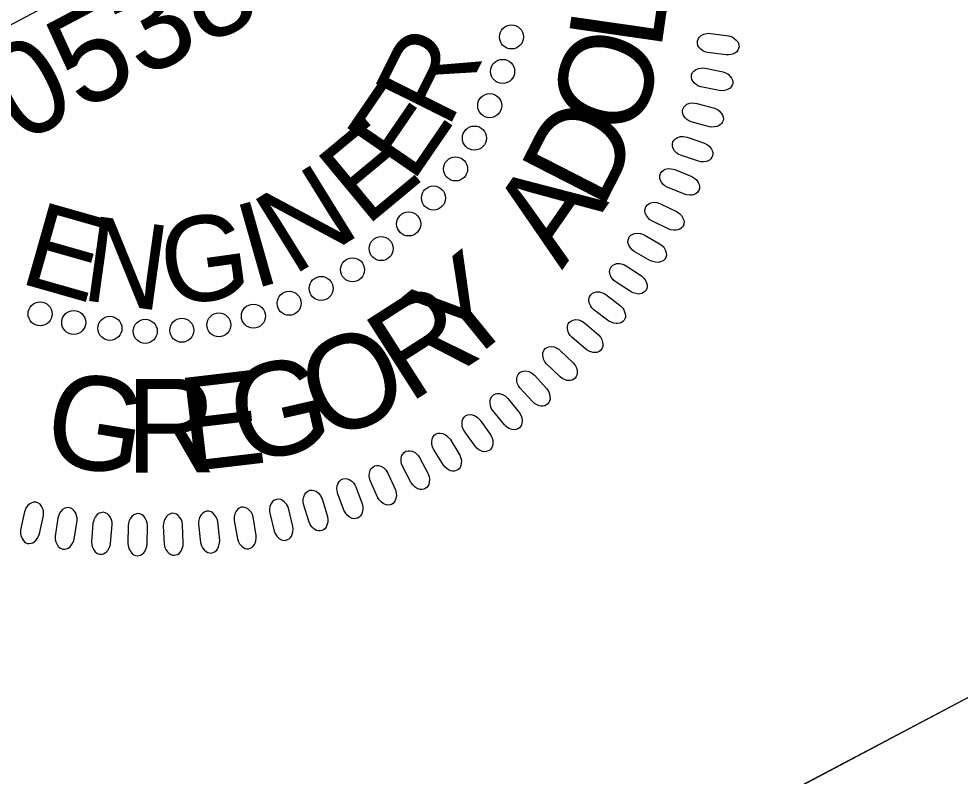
# Model space of a CAD drawing. Extents: x 1486990 to 1489232, y 497582 to 499336.
# Drawn here: x 1488528 to 1488578.8, y 499157.9 to 499198.8 of the extents above; entities that cross this region are included whole.
import ezdxf

# ---------------------------------------------------------------- set-up
doc = ezdxf.new("R2010")
doc.units = 0
for name, color, linetype in [('DTM Contours Minor', 7, 'Continuous'), ('PROF-MAJR', 7, 'Continuous'), ('Prop Drainage Structure Catch Basin Open Throat 1 CELL', 7, 'Continuous'), ('Prop Drainage Structure Drop Inlet Adjust CELL', 7, 'Continuous')]:
    doc.layers.add(name, color=color, linetype=linetype)

msp = doc.modelspace()

# ---------------------------------------------------------------- linework, layer by layer
at = {"layer": 'DTM Contours Minor'}
msp.add_line((1488428.293, 499082.427), (1488605.185, 499175.83), dxfattribs=at)
msp.add_line((1488428.293, 499082.427), (1488605.185, 499175.83), dxfattribs=at)
at = {"layer": 'PROF-MAJR'}
for points in [[(1488565.357, 499197.978), (1488566.34, 499197.837), (1488566.512, 499197.781), (1488566.618, 499197.724), (1488566.741, 499197.615), (1488566.818, 499197.524), (1488566.869, 499197.424), (1488566.889, 499197.337), (1488566.892, 499197.244), (1488566.863, 499197.157), (1488566.825, 499197.064), (1488566.766, 499196.987), (1488566.673, 499196.915), (1488566.602, 499196.876), (1488566.474, 499196.839), (1488566.323, 499196.812), (1488566.193, 499196.812), (1488565.185, 499196.95), (1488565.052, 499196.988), (1488564.945, 499197.04), (1488564.827, 499197.13), (1488564.728, 499197.236), (1488564.675, 499197.323), (1488564.645, 499197.456), (1488564.647, 499197.578), (1488564.696, 499197.693), (1488564.748, 499197.772), (1488564.842, 499197.863), (1488564.992, 499197.939), (1488565.144, 499197.972), (1488565.251, 499197.981)], [(1488565.062, 499196.1), (1488566.035, 499195.897), (1488566.203, 499195.831), (1488566.305, 499195.767), (1488566.421, 499195.65), (1488566.492, 499195.555), (1488566.537, 499195.452), (1488566.551, 499195.363), (1488566.548, 499195.27), (1488566.513, 499195.186), (1488566.47, 499195.095), (1488566.406, 499195.023), (1488566.309, 499194.956), (1488566.236, 499194.922), (1488566.106, 499194.893), (1488565.954, 499194.875), (1488565.824, 499194.884), (1488564.826, 499195.085), (1488564.695, 499195.131), (1488564.592, 499195.19), (1488564.481, 499195.287), (1488564.388, 499195.399), (1488564.341, 499195.49), (1488564.319, 499195.624), (1488564.329, 499195.746), (1488564.385, 499195.858), (1488564.442, 499195.932), (1488564.542, 499196.017), (1488564.695, 499196.083), (1488564.849, 499196.107), (1488564.957, 499196.109)], [(1488564.606, 499194.199), (1488565.564, 499193.936), (1488565.727, 499193.86), (1488565.825, 499193.789), (1488565.934, 499193.665), (1488565.998, 499193.566), (1488566.037, 499193.461), (1488566.045, 499193.371), (1488566.036, 499193.279), (1488565.997, 499193.195), (1488565.948, 499193.108), (1488565.88, 499193.04), (1488565.778, 499192.979), (1488565.704, 499192.95), (1488565.572, 499192.929), (1488565.419, 499192.921), (1488565.29, 499192.937), (1488564.307, 499193.202), (1488564.179, 499193.255), (1488564.079, 499193.321), (1488563.974, 499193.425), (1488563.889, 499193.542), (1488563.848, 499193.635), (1488563.834, 499193.771), (1488563.852, 499193.892), (1488563.915, 499194), (1488563.976, 499194.071), (1488564.081, 499194.149), (1488564.239, 499194.206), (1488564.394, 499194.22), (1488564.502, 499194.216)], [(1488564.092, 499192.376), (1488565.032, 499192.053), (1488565.19, 499191.967), (1488565.284, 499191.89), (1488565.384, 499191.76), (1488565.443, 499191.656), (1488565.474, 499191.549), (1488565.477, 499191.459), (1488565.463, 499191.367), (1488565.418, 499191.287), (1488565.364, 499191.203), (1488565.291, 499191.139), (1488565.186, 499191.085), (1488565.109, 499191.06), (1488564.977, 499191.048), (1488564.824, 499191.049), (1488564.696, 499191.074), (1488563.731, 499191.399), (1488563.607, 499191.461), (1488563.512, 499191.533), (1488563.413, 499191.643), (1488563.336, 499191.765), (1488563.301, 499191.861), (1488563.296, 499191.997), (1488563.32, 499192.117), (1488563.39, 499192.22), (1488563.456, 499192.287), (1488563.566, 499192.359), (1488563.726, 499192.406), (1488563.882, 499192.41), (1488563.989, 499192.399)], [(1488563.43, 499190.625), (1488564.348, 499190.244), (1488564.501, 499190.148), (1488564.589, 499190.065), (1488564.681, 499189.929), (1488564.733, 499189.822), (1488564.757, 499189.713), (1488564.755, 499189.623), (1488564.735, 499189.533), (1488564.685, 499189.456), (1488564.625, 499189.375), (1488564.548, 499189.315), (1488564.441, 499189.268), (1488564.363, 499189.248), (1488564.23, 499189.244), (1488564.077, 499189.255), (1488563.951, 499189.288), (1488563.009, 499189.673), (1488562.889, 499189.743), (1488562.799, 499189.82), (1488562.707, 499189.936), (1488562.637, 499190.063), (1488562.608, 499190.161), (1488562.612, 499190.297), (1488562.643, 499190.415), (1488562.72, 499190.514), (1488562.79, 499190.577), (1488562.904, 499190.641), (1488563.067, 499190.678), (1488563.223, 499190.673), (1488563.329, 499190.655)], [(1488562.658, 499188.782), (1488563.549, 499188.344), (1488563.695, 499188.239), (1488563.779, 499188.152), (1488563.862, 499188.009), (1488563.907, 499187.899), (1488563.925, 499187.789), (1488563.916, 499187.699), (1488563.89, 499187.61), (1488563.836, 499187.536), (1488563.772, 499187.46), (1488563.691, 499187.405), (1488563.581, 499187.365), (1488563.502, 499187.349), (1488563.369, 499187.354), (1488563.217, 499187.375), (1488563.093, 499187.415), (1488562.177, 499187.858), (1488562.062, 499187.936), (1488561.977, 499188.018), (1488561.892, 499188.14), (1488561.83, 499188.271), (1488561.807, 499188.371), (1488561.82, 499188.506), (1488561.859, 499188.622), (1488561.942, 499188.716), (1488562.015, 499188.775), (1488562.133, 499188.832), (1488562.298, 499188.858), (1488562.454, 499188.843), (1488562.558, 499188.818)], [(1488561.768, 499187.096), (1488562.631, 499186.602), (1488562.77, 499186.488), (1488562.847, 499186.395), (1488562.921, 499186.248), (1488562.96, 499186.135), (1488562.97, 499186.024), (1488562.957, 499185.935), (1488562.925, 499185.848), (1488562.866, 499185.777), (1488562.797, 499185.705), (1488562.713, 499185.655), (1488562.601, 499185.622), (1488562.521, 499185.612), (1488562.388, 499185.625), (1488562.238, 499185.655), (1488562.117, 499185.703), (1488561.231, 499186.203), (1488561.12, 499186.288), (1488561.04, 499186.375), (1488560.964, 499186.502), (1488560.911, 499186.637), (1488560.894, 499186.738), (1488560.915, 499186.872), (1488560.961, 499186.986), (1488561.049, 499187.075), (1488561.127, 499187.128), (1488561.247, 499187.178), (1488561.415, 499187.193), (1488561.568, 499187.168), (1488561.671, 499187.137)], [(1488560.798, 499185.432), (1488561.628, 499184.885), (1488561.759, 499184.763), (1488561.831, 499184.665), (1488561.896, 499184.514), (1488561.926, 499184.399), (1488561.93, 499184.288), (1488561.911, 499184.199), (1488561.874, 499184.114), (1488561.811, 499184.048), (1488561.737, 499183.98), (1488561.651, 499183.936), (1488561.536, 499183.91), (1488561.456, 499183.904), (1488561.324, 499183.926), (1488561.176, 499183.965), (1488561.058, 499184.021), (1488560.205, 499184.576), (1488560.1, 499184.666), (1488560.026, 499184.759), (1488559.958, 499184.891), (1488559.913, 499185.028), (1488559.902, 499185.13), (1488559.932, 499185.263), (1488559.985, 499185.373), (1488560.079, 499185.456), (1488560.159, 499185.505), (1488560.283, 499185.547), (1488560.451, 499185.552), (1488560.603, 499185.517), (1488560.703, 499185.48)], [(1488559.695, 499183.875), (1488560.489, 499183.277), (1488560.613, 499183.147), (1488560.678, 499183.045), (1488560.733, 499182.889), (1488560.757, 499182.773), (1488560.753, 499182.662), (1488560.729, 499182.575), (1488560.686, 499182.492), (1488560.619, 499182.43), (1488560.541, 499182.367), (1488560.452, 499182.328), (1488560.336, 499182.309), (1488560.256, 499182.309), (1488560.126, 499182.338), (1488559.981, 499182.387), (1488559.866, 499182.45), (1488559.05, 499183.058), (1488558.951, 499183.155), (1488558.882, 499183.252), (1488558.823, 499183.387), (1488558.787, 499183.528), (1488558.783, 499183.63), (1488558.82, 499183.761), (1488558.881, 499183.867), (1488558.979, 499183.944), (1488559.062, 499183.987), (1488559.188, 499184.022), (1488559.356, 499184.016), (1488559.506, 499183.972), (1488559.604, 499183.928)], [(1488558.552, 499182.349), (1488559.307, 499181.702), (1488559.422, 499181.563), (1488559.481, 499181.458), (1488559.526, 499181.3), (1488559.542, 499181.182), (1488559.532, 499181.071), (1488559.502, 499180.986), (1488559.455, 499180.906), (1488559.384, 499180.848), (1488559.302, 499180.79), (1488559.21, 499180.757), (1488559.094, 499180.745), (1488559.013, 499180.75), (1488558.886, 499180.788), (1488558.744, 499180.846), (1488558.634, 499180.916), (1488557.857, 499181.573), (1488557.764, 499181.676), (1488557.702, 499181.777), (1488557.651, 499181.917), (1488557.624, 499182.059), (1488557.626, 499182.161), (1488557.671, 499182.289), (1488557.739, 499182.392), (1488557.842, 499182.463), (1488557.928, 499182.501), (1488558.056, 499182.526), (1488558.223, 499182.51), (1488558.37, 499182.458), (1488558.464, 499182.408)], [(1488557.236, 499180.866), (1488557.948, 499180.174), (1488558.055, 499180.028), (1488558.107, 499179.919), (1488558.142, 499179.758), (1488558.151, 499179.64), (1488558.134, 499179.529), (1488558.098, 499179.446), (1488558.046, 499179.37), (1488557.971, 499179.316), (1488557.887, 499179.263), (1488557.793, 499179.236), (1488557.676, 499179.232), (1488557.595, 499179.242), (1488557.471, 499179.288), (1488557.332, 499179.354), (1488557.227, 499179.431), (1488556.493, 499180.136), (1488556.407, 499180.245), (1488556.351, 499180.349), (1488556.309, 499180.491), (1488556.291, 499180.635), (1488556.3, 499180.737), (1488556.354, 499180.862), (1488556.426, 499180.96), (1488556.534, 499181.024), (1488556.622, 499181.057), (1488556.752, 499181.075), (1488556.917, 499181.048), (1488557.06, 499180.986), (1488557.152, 499180.931)], [(1488555.848, 499179.518), (1488556.517, 499178.782), (1488556.613, 499178.63), (1488556.658, 499178.518), (1488556.683, 499178.355), (1488556.685, 499178.236), (1488556.661, 499178.127), (1488556.62, 499178.047), (1488556.563, 499177.974), (1488556.486, 499177.925), (1488556.397, 499177.877), (1488556.302, 499177.856), (1488556.185, 499177.859), (1488556.106, 499177.874), (1488555.984, 499177.928), (1488555.85, 499178.003), (1488555.75, 499178.086), (1488555.061, 499178.835), (1488554.982, 499178.95), (1488554.933, 499179.057), (1488554.9, 499179.202), (1488554.891, 499179.347), (1488554.906, 499179.448), (1488554.968, 499179.569), (1488555.047, 499179.663), (1488555.158, 499179.72), (1488555.248, 499179.747), (1488555.378, 499179.757), (1488555.542, 499179.72), (1488555.681, 499179.649), (1488555.769, 499179.587)], [(1488554.415, 499178.268), (1488555.035, 499177.491), (1488555.123, 499177.334), (1488555.161, 499177.219), (1488555.176, 499177.055), (1488555.169, 499176.936), (1488555.139, 499176.829), (1488555.093, 499176.751), (1488555.031, 499176.681), (1488554.95, 499176.638), (1488554.86, 499176.596), (1488554.763, 499176.581), (1488554.647, 499176.591), (1488554.569, 499176.611), (1488554.45, 499176.672), (1488554.322, 499176.755), (1488554.227, 499176.845), (1488553.586, 499177.636), (1488553.515, 499177.754), (1488553.473, 499177.866), (1488553.449, 499178.012), (1488553.449, 499178.157), (1488553.47, 499178.257), (1488553.539, 499178.374), (1488553.624, 499178.462), (1488553.739, 499178.512), (1488553.83, 499178.534), (1488553.961, 499178.535), (1488554.122, 499178.488), (1488554.256, 499178.408), (1488554.34, 499178.342)], [(1488552.913, 499177.097), (1488553.483, 499176.284), (1488553.56, 499176.121), (1488553.591, 499176.004), (1488553.595, 499175.839), (1488553.582, 499175.721), (1488553.544, 499175.616), (1488553.494, 499175.541), (1488553.428, 499175.476), (1488553.345, 499175.437), (1488553.251, 499175.401), (1488553.155, 499175.392), (1488553.038, 499175.41), (1488552.962, 499175.435), (1488552.847, 499175.503), (1488552.724, 499175.594), (1488552.635, 499175.689), (1488552.046, 499176.519), (1488551.982, 499176.642), (1488551.947, 499176.756), (1488551.932, 499176.903), (1488551.941, 499177.047), (1488551.969, 499177.146), (1488552.045, 499177.259), (1488552.136, 499177.342), (1488552.253, 499177.384), (1488552.346, 499177.4), (1488552.476, 499177.393), (1488552.634, 499177.336), (1488552.763, 499177.248), (1488552.842, 499177.176)], [(1488551.292, 499176.063), (1488551.81, 499175.215), (1488551.877, 499175.048), (1488551.9, 499174.93), (1488551.894, 499174.765), (1488551.873, 499174.648), (1488551.829, 499174.545), (1488551.774, 499174.474), (1488551.705, 499174.413), (1488551.619, 499174.38), (1488551.524, 499174.349), (1488551.426, 499174.346), (1488551.311, 499174.371), (1488551.236, 499174.401), (1488551.127, 499174.476), (1488551.01, 499174.575), (1488550.927, 499174.676), (1488550.39, 499175.541), (1488550.334, 499175.667), (1488550.307, 499175.783), (1488550.302, 499175.931), (1488550.32, 499176.075), (1488550.353, 499176.171), (1488550.436, 499176.279), (1488550.532, 499176.356), (1488550.651, 499176.391), (1488550.745, 499176.401), (1488550.875, 499176.386), (1488551.029, 499176.319), (1488551.152, 499176.223), (1488551.227, 499176.147)], [(1488549.643, 499175.08), (1488550.107, 499174.201), (1488550.163, 499174.03), (1488550.178, 499173.91), (1488550.162, 499173.746), (1488550.134, 499173.63), (1488550.084, 499173.531), (1488550.024, 499173.463), (1488549.951, 499173.407), (1488549.864, 499173.378), (1488549.766, 499173.354), (1488549.669, 499173.357), (1488549.556, 499173.39), (1488549.483, 499173.424), (1488549.378, 499173.506), (1488549.268, 499173.612), (1488549.191, 499173.718), (1488548.711, 499174.615), (1488548.663, 499174.744), (1488548.642, 499174.862), (1488548.646, 499175.01), (1488548.673, 499175.152), (1488548.713, 499175.247), (1488548.803, 499175.349), (1488548.903, 499175.419), (1488549.024, 499175.447), (1488549.118, 499175.451), (1488549.247, 499175.428), (1488549.396, 499175.352), (1488549.513, 499175.248), (1488549.583, 499175.167)], [(1488547.93, 499174.241), (1488548.338, 499173.334), (1488548.383, 499173.16), (1488548.392, 499173.039), (1488548.365, 499172.877), (1488548.33, 499172.763), (1488548.274, 499172.668), (1488548.21, 499172.603), (1488548.133, 499172.551), (1488548.044, 499172.529), (1488547.946, 499172.511), (1488547.849, 499172.52), (1488547.738, 499172.559), (1488547.667, 499172.598), (1488547.568, 499172.686), (1488547.464, 499172.799), (1488547.394, 499172.91), (1488546.971, 499173.835), (1488546.931, 499173.968), (1488546.918, 499174.086), (1488546.931, 499174.233), (1488546.967, 499174.374), (1488547.013, 499174.465), (1488547.109, 499174.561), (1488547.213, 499174.626), (1488547.337, 499174.646), (1488547.43, 499174.644), (1488547.557, 499174.613), (1488547.702, 499174.527), (1488547.812, 499174.417), (1488547.876, 499174.331)], [(1488546.196, 499173.505), (1488546.546, 499172.575), (1488546.58, 499172.398), (1488546.581, 499172.277), (1488546.544, 499172.117), (1488546.502, 499172.006), (1488546.44, 499171.913), (1488546.372, 499171.853), (1488546.292, 499171.806), (1488546.202, 499171.79), (1488546.102, 499171.778), (1488546.006, 499171.793), (1488545.899, 499171.84), (1488545.83, 499171.883), (1488545.736, 499171.977), (1488545.64, 499172.096), (1488545.577, 499172.21), (1488545.213, 499173.16), (1488545.182, 499173.295), (1488545.176, 499173.414), (1488545.198, 499173.561), (1488545.243, 499173.699), (1488545.294, 499173.787), (1488545.396, 499173.877), (1488545.504, 499173.935), (1488545.629, 499173.947), (1488545.722, 499173.939), (1488545.847, 499173.9), (1488545.985, 499173.805), (1488546.088, 499173.688), (1488546.148, 499173.599)], [(1488544.378, 499172.843), (1488544.669, 499171.893), (1488544.692, 499171.714), (1488544.685, 499171.594), (1488544.639, 499171.436), (1488544.589, 499171.328), (1488544.521, 499171.239), (1488544.45, 499171.184), (1488544.367, 499171.142), (1488544.276, 499171.131), (1488544.176, 499171.125), (1488544.081, 499171.147), (1488543.977, 499171.199), (1488543.911, 499171.247), (1488543.824, 499171.347), (1488543.735, 499171.472), (1488543.679, 499171.59), (1488543.376, 499172.561), (1488543.353, 499172.698), (1488543.355, 499172.817), (1488543.386, 499172.961), (1488543.44, 499173.096), (1488543.496, 499173.181), (1488543.603, 499173.264), (1488543.715, 499173.315), (1488543.84, 499173.32), (1488543.933, 499173.306), (1488544.055, 499173.26), (1488544.187, 499173.156), (1488544.282, 499173.033), (1488544.335, 499172.94)], [(1488528.303, 499172.142), (1488528.1, 499171.169), (1488528.094, 499170.989), (1488528.112, 499170.869), (1488528.173, 499170.716), (1488528.233, 499170.613), (1488528.308, 499170.531), (1488528.384, 499170.482), (1488528.47, 499170.448), (1488528.561, 499170.446), (1488528.662, 499170.45), (1488528.754, 499170.48), (1488528.854, 499170.542), (1488528.915, 499170.595), (1488528.993, 499170.702), (1488529.07, 499170.835), (1488529.114, 499170.958), (1488529.327, 499171.953), (1488529.338, 499172.091), (1488529.325, 499172.21), (1488529.28, 499172.35), (1488529.215, 499172.48), (1488529.151, 499172.56), (1488529.036, 499172.632), (1488528.921, 499172.673), (1488528.796, 499172.666), (1488528.704, 499172.643), (1488528.587, 499172.586), (1488528.465, 499172.471), (1488528.381, 499172.339), (1488528.336, 499172.242)], [(1488541.558, 499172.074), (1488541.789, 499171.108), (1488541.859, 499170.943), (1488541.927, 499170.842), (1488542.047, 499170.729), (1488542.144, 499170.661), (1488542.248, 499170.62), (1488542.338, 499170.608), (1488542.43, 499170.613), (1488542.514, 499170.65), (1488542.603, 499170.697), (1488542.674, 499170.763), (1488542.738, 499170.861), (1488542.77, 499170.935), (1488542.794, 499171.066), (1488542.808, 499171.219), (1488542.795, 499171.349), (1488542.565, 499172.34), (1488542.515, 499172.469), (1488542.453, 499172.571), (1488542.353, 499172.68), (1488542.239, 499172.769), (1488542.147, 499172.813), (1488542.012, 499172.831), (1488541.891, 499172.818), (1488541.78, 499172.758), (1488541.707, 499172.699), (1488541.625, 499172.597), (1488541.564, 499172.441), (1488541.544, 499172.287), (1488541.545, 499172.179)], [(1488530.108, 499171.813), (1488529.968, 499170.829), (1488529.972, 499170.649), (1488529.998, 499170.531), (1488530.068, 499170.382), (1488530.134, 499170.283), (1488530.215, 499170.206), (1488530.294, 499170.162), (1488530.382, 499170.133), (1488530.474, 499170.136), (1488530.573, 499170.147), (1488530.664, 499170.182), (1488530.759, 499170.25), (1488530.816, 499170.307), (1488530.887, 499170.42), (1488530.956, 499170.557), (1488530.993, 499170.682), (1488531.143, 499171.688), (1488531.145, 499171.827), (1488531.124, 499171.944), (1488531.071, 499172.082), (1488530.998, 499172.208), (1488530.929, 499172.282), (1488530.81, 499172.349), (1488530.692, 499172.382), (1488530.567, 499172.367), (1488530.478, 499172.339), (1488530.364, 499172.274), (1488530.249, 499172.151), (1488530.174, 499172.015), (1488530.136, 499171.914)], [(1488532.005, 499171.521), (1488531.927, 499170.53), (1488531.942, 499170.35), (1488531.975, 499170.234), (1488532.055, 499170.09), (1488532.126, 499169.995), (1488532.212, 499169.924), (1488532.294, 499169.884), (1488532.383, 499169.861), (1488532.475, 499169.87), (1488532.574, 499169.886), (1488532.662, 499169.928), (1488532.753, 499170.002), (1488532.806, 499170.063), (1488532.87, 499170.179), (1488532.93, 499170.32), (1488532.958, 499170.447), (1488533.045, 499171.461), (1488533.038, 499171.6), (1488533.011, 499171.715), (1488532.949, 499171.85), (1488532.867, 499171.97), (1488532.793, 499172.041), (1488532.671, 499172.1), (1488532.552, 499172.125), (1488532.428, 499172.102), (1488532.34, 499172.069), (1488532.231, 499171.997), (1488532.124, 499171.868), (1488532.058, 499171.726), (1488532.025, 499171.624)], [(1488533.91, 499171.413), (1488533.894, 499170.42), (1488533.921, 499170.242), (1488533.961, 499170.128), (1488534.05, 499169.989), (1488534.127, 499169.899), (1488534.217, 499169.833), (1488534.301, 499169.799), (1488534.392, 499169.781), (1488534.482, 499169.796), (1488534.58, 499169.819), (1488534.666, 499169.865), (1488534.752, 499169.945), (1488534.801, 499170.008), (1488534.858, 499170.129), (1488534.909, 499170.274), (1488534.929, 499170.403), (1488534.952, 499171.42), (1488534.936, 499171.557), (1488534.901, 499171.672), (1488534.831, 499171.802), (1488534.743, 499171.917), (1488534.665, 499171.983), (1488534.538, 499172.033), (1488534.418, 499172.051), (1488534.296, 499172.021), (1488534.211, 499171.982), (1488534.106, 499171.903), (1488534.008, 499171.767), (1488533.95, 499171.623), (1488533.924, 499171.519)], [(1488535.804, 499171.4), (1488535.85, 499170.408), (1488535.888, 499170.232), (1488535.936, 499170.121), (1488536.033, 499169.988), (1488536.116, 499169.902), (1488536.209, 499169.842), (1488536.295, 499169.814), (1488536.387, 499169.802), (1488536.477, 499169.823), (1488536.572, 499169.851), (1488536.655, 499169.903), (1488536.736, 499169.988), (1488536.782, 499170.055), (1488536.83, 499170.178), (1488536.872, 499170.326), (1488536.884, 499170.456), (1488536.844, 499171.473), (1488536.819, 499171.609), (1488536.777, 499171.72), (1488536.699, 499171.846), (1488536.603, 499171.955), (1488536.521, 499172.016), (1488536.392, 499172.058), (1488536.27, 499172.069), (1488536.151, 499172.031), (1488536.068, 499171.987), (1488535.969, 499171.902), (1488535.879, 499171.76), (1488535.831, 499171.612), (1488535.812, 499171.506)], [(1488537.709, 499171.484), (1488537.817, 499170.496), (1488537.867, 499170.322), (1488537.921, 499170.215), (1488538.026, 499170.088), (1488538.114, 499170.008), (1488538.212, 499169.954), (1488538.299, 499169.931), (1488538.392, 499169.925), (1488538.479, 499169.951), (1488538.573, 499169.985), (1488538.653, 499170.042), (1488538.728, 499170.132), (1488538.769, 499170.202), (1488538.81, 499170.328), (1488538.842, 499170.478), (1488538.847, 499170.608), (1488538.742, 499171.621), (1488538.709, 499171.755), (1488538.66, 499171.863), (1488538.574, 499171.984), (1488538.472, 499172.087), (1488538.386, 499172.143), (1488538.255, 499172.177), (1488538.132, 499172.18), (1488538.016, 499172.134), (1488537.936, 499172.085), (1488537.842, 499171.994), (1488537.761, 499171.847), (1488537.723, 499171.696), (1488537.71, 499171.589)], [(1488539.632, 499171.674), (1488539.802, 499170.694), (1488539.862, 499170.524), (1488539.923, 499170.42), (1488540.036, 499170.3), (1488540.129, 499170.226), (1488540.23, 499170.178), (1488540.318, 499170.161), (1488540.411, 499170.16), (1488540.498, 499170.192), (1488540.589, 499170.232), (1488540.664, 499170.294), (1488540.734, 499170.389), (1488540.771, 499170.461), (1488540.804, 499170.589), (1488540.826, 499170.741), (1488540.823, 499170.871), (1488540.655, 499171.875), (1488540.613, 499172.008), (1488540.558, 499172.113), (1488540.464, 499172.227), (1488540.356, 499172.323), (1488540.267, 499172.374), (1488540.133, 499172.4), (1488540.011, 499172.395), (1488539.897, 499172.342), (1488539.821, 499172.288), (1488539.733, 499172.191), (1488539.662, 499172.039), (1488539.632, 499171.886), (1488539.627, 499171.779)]]:
    msp.add_lwpolyline(points, close=True, dxfattribs=at)
for centre in [(1488554.603, 499197.783), (1488554.125, 499195.925), (1488553.427, 499194.075), (1488552.6, 499192.325), (1488551.585, 499190.658), (1488550.391, 499189.09), (1488549.052, 499187.69), (1488547.567, 499186.358), (1488546.02, 499185.213), (1488544.326, 499184.209), (1488542.598, 499183.406), (1488529.15, 499182.837), (1488540.666, 499182.714), (1488530.964, 499182.372), (1488532.919, 499182.054), (1488538.801, 499182.241), (1488534.827, 499181.894), (1488536.802, 499181.951)]:
    msp.add_circle(centre, 0.649, dxfattribs=at)
at = {"layer": 'Prop Drainage Structure Catch Basin Open Throat 1 CELL'}
for points in [[(1488464.232, 499228.609), (1488552.644, 499275.307), (1488605.191, 499175.819), (1488516.767, 499129.115)], [(1487698.943, 497679.61), (1487208.658, 498608.086), (1488358.213, 499215.12), (1488428.293, 499082.427), (1488605.191, 499175.819), (1489025.397, 498380.008)]]:
    msp.add_lwpolyline(points, close=True, dxfattribs=at)
at = {"layer": 'Prop Drainage Structure Drop Inlet Adjust CELL'}
msp.add_lwpolyline([(1488425.501, 499144.548), (1488414.528, 499165.329), (1488544.519, 499233.968), (1488555.492, 499213.187)], close=True, dxfattribs=at)

# ---------------------------------------------------------------- texts
at = {"layer": 'PROF-MAJR'}
for s, height, rotation, p in [('053892', 5.0514, 27.8351, (1488528.033, 499191.968)), ('L', 5.051, 81.8069, (1488562.666, 499196.986)), ('R', 4.592, 63.5173, (1488551.171, 499192.758)), ('O', 5.051, 71.6258, (1488561.287, 499192.195)), ('E', 4.592, 55.5775, (1488549.244, 499189.85)), ('D', 5.051, 62.9284, (1488559.452, 499188.349)), ('E', 4.592, 39.6979, (1488546.754, 499187.506)), ('N', 4.592, 31.7581, (1488542.795, 499184.858)), ('A', 5.051, 55.1428, (1488557.333, 499185.176)), ('E', 4.592, 344.1193, (1488527.933, 499184.531)), ('I', 4.592, 15.8785, (1488540.645, 499184.155)), ('G', 4.592, 7.9387, (1488535.974, 499183.235)), ('N', 4.592, 352.0591, (1488531.297, 499183.601)), ('Y', 5.051, 39.1906, (1488551.761, 499179.722)), ('R', 5.051, 32.6028, (1488549.057, 499177.957)), ('O', 5.051, 22.4217, (1488544.528, 499175.871)), ('G', 5.051, 12.9757, (1488540.057, 499174.68)), ('G', 5.051, 350.6807, (1488529.194, 499174.86)), ('E', 5.051, 6.7145, (1488537.012, 499174.302)), ('R', 5.051, 0.1268, (1488533.783, 499174.266))]:
    msp.add_text(s, height=height, rotation=rotation, dxfattribs=at).set_placement(p)
at = {"layer": 'Prop Drainage Structure Drop Inlet Adjust CELL'}
for s, height, p in [('INCOMPLETE PLANS', 11.52, (1488427.952, 499159.074)), ('DO NOT USE FOR R/W ACQUISITION', 5.76, (1488434.071, 499154.445))]:
    msp.add_text(s, height=height, rotation=27.8351, dxfattribs=at).set_placement(p)

doc.saveas('drawing.dxf')
